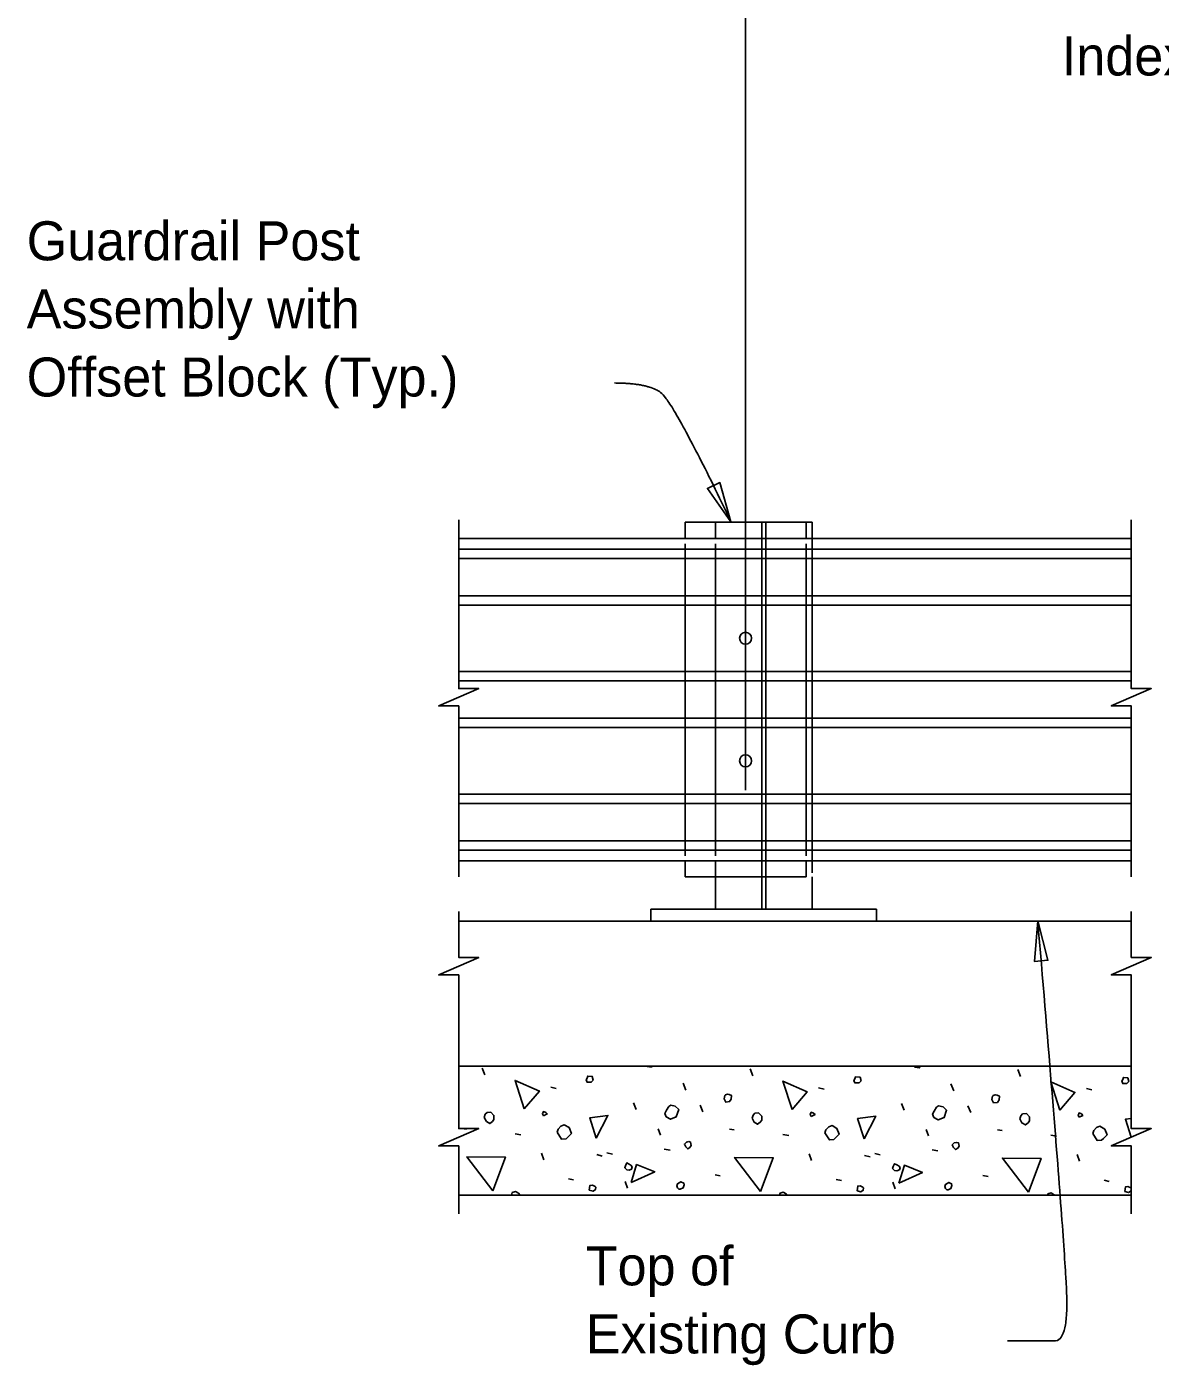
# Model space of a CAD drawing. Extents: x 21516.9 to 21589, y 56154.7 to 56194.3.
# Drawn here: x 21518.18 to 21524.04, y 56169.83 to 56176.75 of the extents above; entities that cross this region are included whole.
import ezdxf

# ---------------------------------------------------------------- set-up
doc = ezdxf.new("R2010")
doc.units = 0
for name, color, linetype in [('AdhocPoint_dp', 7, 'Continuous'), ('Border', 7, 'Continuous'), ('Patterning', 7, 'Continuous'), ('PlotBorder_dp', 7, 'Continuous'), ('TextMisc', 7, 'Continuous')]:
    doc.layers.add(name, color=color, linetype=linetype)

msp = doc.modelspace()

# ---------------------------------------------------------------- linework, layer by layer
at = {"layer": 'AdhocPoint_dp'}
for p, q in [((21523.8864, 56172.1237), (21520.4095, 56172.1237)), ((21520.4095, 56171.3737), (21523.8864, 56171.3737)), ((21523.8864, 56170.707), (21520.4095, 56170.707))]:
    msp.add_line(p, q, dxfattribs=at)
at = {"layer": 'Border'}
for p, q in [((21521.9758, 56172.1863), (21521.9758, 56174.1863)), ((21521.9967, 56172.1863), (21521.9967, 56174.1863)), ((21522.2363, 56174.1863), (21522.2363, 56172.3733)), ((21521.7363, 56174.0744), (21521.7363, 56172.4625))]:
    msp.add_line(p, q, dxfattribs=at)
at = {"layer": 'Patterning'}
for p, q in [((21521.58, 56174.1863), (21522.205, 56174.1863)), ((21521.58, 56174.1863), (21521.58, 56174.1029)), ((21522.205, 56174.1863), (21522.205, 56174.1029)), ((21521.58, 56174.0744), (21521.58, 56172.4625)), ((21522.205, 56174.0744), (21522.205, 56172.4625)), ((21521.58, 56172.3529), (21521.58, 56172.4363)), ((21522.205, 56172.3529), (21522.205, 56172.4363)), ((21521.58, 56172.3529), (21522.205, 56172.3529)), ((21520.545, 56171.3288), (21520.5309, 56171.3641)), ((21521.9297, 56171.3252), (21521.9156, 56171.3606)), ((21523.3144, 56171.3217), (21523.3002, 56171.3571)), ((21521.5838, 56171.2504), (21521.5697, 56171.2857)), ((21522.9685, 56171.2468), (21522.9544, 56171.2822)), ((21520.8856, 56171.2663), (21520.9139, 56171.2592)), ((21522.2703, 56171.2627), (21522.2985, 56171.2557)), ((21523.6549, 56171.2592), (21523.6832, 56171.2521)), ((21521.3275, 56171.1496), (21521.3134, 56171.185)), ((21521.6716, 56171.1379), (21521.6575, 56171.1732)), ((21522.7122, 56171.1461), (21522.6981, 56171.1814)), ((21523.0563, 56171.1343), (21523.0421, 56171.1697)), ((21520.4248, 56171.053), (21520.4496, 56171.0495)), ((21520.7006, 56171.0247), (21520.7306, 56171.0194)), ((21521.453, 56171.017), (21521.4407, 56171.0506)), ((21521.8095, 56171.0495), (21521.8342, 56171.0459)), ((21522.0853, 56171.0212), (21522.1153, 56171.0159)), ((21522.8377, 56171.0135), (21522.8253, 56171.0471)), ((21523.1942, 56171.0459), (21523.2189, 56171.0424)), ((21523.4699, 56171.0177), (21523.5, 56171.0123)), ((21520.8491, 56170.8904), (21520.8367, 56170.924)), ((21521.1755, 56170.9269), (21521.2038, 56170.9198)), ((21521.4719, 56170.9452), (21521.5019, 56170.9399)), ((21522.5602, 56170.9233), (21522.5885, 56170.9163)), ((21522.8565, 56170.9416), (21522.8866, 56170.9363)), ((21521.1231, 56170.9169), (21521.1514, 56170.9098)), ((21522.2338, 56170.8868), (21522.2214, 56170.9204)), ((21522.5078, 56170.9134), (21522.536, 56170.9063)), ((21523.6184, 56170.8833), (21523.6061, 56170.9169)), ((21520.9764, 56170.7914), (21521.0029, 56170.7861)), ((21521.7353, 56170.8126), (21521.7618, 56170.8073)), ((21522.361, 56170.7878), (21522.3876, 56170.7825)), ((21523.1199, 56170.8091), (21523.1464, 56170.8038)), ((21523.7457, 56170.7843), (21523.7722, 56170.779)), ((21521.2816, 56170.7443), (21521.2692, 56170.7779)), ((21522.6662, 56170.7407), (21522.6539, 56170.7743))]:
    msp.add_line(p, q, dxfattribs=at)
for points in [[(21521.3833, 56171.3737), (21521.3841, 56171.3723), (21521.4053, 56171.3688), (21521.408, 56171.3737)], [(21522.7661, 56171.3737), (21522.7688, 56171.3688), (21522.79, 56171.3653), (21522.7947, 56171.3737)], [(21520.7483, 56171.1538), (21520.7006, 56171.3005), (21520.8261, 56171.2457), (21520.7483, 56171.1538)], [(21521.073, 56171.291), (21521.0942, 56171.291), (21521.1048, 56171.3016), (21521.0995, 56171.3211), (21521.0765, 56171.3228), (21521.073, 56171.3122), (21521.0677, 56171.3034), (21521.073, 56171.291), (21521.0694, 56171.2946)], [(21522.133, 56171.1502), (21522.0853, 56171.297), (21522.2108, 56171.2422), (21522.133, 56171.1502)], [(21522.4576, 56171.2875), (21522.4789, 56171.2875), (21522.4895, 56171.2981), (21522.4842, 56171.3175), (21522.4612, 56171.3193), (21522.4576, 56171.3087), (21522.4523, 56171.2999), (21522.4576, 56171.2875), (21522.4541, 56171.291)], [(21523.5177, 56171.1467), (21523.4699, 56171.2934), (21523.5955, 56171.2386), (21523.5177, 56171.1467)], [(21523.8423, 56171.284), (21523.8635, 56171.284), (21523.8741, 56171.2946), (21523.8688, 56171.314), (21523.8459, 56171.3158), (21523.8423, 56171.3052), (21523.837, 56171.2963), (21523.8423, 56171.284), (21523.8388, 56171.2875)], [(21521.7812, 56171.205), (21521.7901, 56171.1891), (21521.8095, 56171.1909), (21521.8183, 56171.2033), (21521.8201, 56171.2227), (21521.8077, 56171.228), (21521.7989, 56171.2298), (21521.7883, 56171.2262), (21521.7847, 56171.2227), (21521.7812, 56171.205)], [(21523.1659, 56171.2015), (21523.1747, 56171.1856), (21523.1942, 56171.1874), (21523.203, 56171.1997), (21523.2048, 56171.2192), (21523.1924, 56171.2245), (21523.1836, 56171.2262), (21523.173, 56171.2227), (21523.1694, 56171.2192), (21523.1659, 56171.2015)], [(21520.5415, 56171.1096), (21520.5521, 56171.0884), (21520.5698, 56171.0778), (21520.5839, 56171.0884), (21520.591, 56171.099), (21520.591, 56171.1202), (21520.5751, 56171.1361), (21520.5556, 56171.1343), (21520.5468, 56171.1255), (21520.5415, 56171.1096)], [(21520.8473, 56171.1184), (21520.8668, 56171.1273), (21520.8597, 56171.1343), (21520.8473, 56171.1396), (21520.842, 56171.1273), (21520.8473, 56171.1184)], [(21521.4813, 56171.1125), (21521.5043, 56171.1001), (21521.5344, 56171.1125), (21521.5467, 56171.1496), (21521.529, 56171.1673), (21521.5061, 56171.1726), (21521.4955, 56171.1655), (21521.4831, 56171.1461), (21521.4742, 56171.1302), (21521.4813, 56171.1125)], [(21521.9262, 56171.106), (21521.9368, 56171.0848), (21521.9545, 56171.0742), (21521.9686, 56171.0848), (21521.9757, 56171.0954), (21521.9757, 56171.1166), (21521.9598, 56171.1326), (21521.9403, 56171.1308), (21521.9315, 56171.1219), (21521.9262, 56171.106)], [(21522.232, 56171.1149), (21522.2514, 56171.1237), (21522.2444, 56171.1308), (21522.232, 56171.1361), (21522.2267, 56171.1237), (21522.232, 56171.1149)], [(21522.866, 56171.1089), (21522.889, 56171.0966), (21522.919, 56171.1089), (21522.9314, 56171.1461), (21522.9137, 56171.1638), (21522.8907, 56171.1691), (21522.8801, 56171.162), (21522.8678, 56171.1425), (21522.8589, 56171.1266), (21522.866, 56171.1089)], [(21523.6167, 56171.1113), (21523.6361, 56171.1202), (21523.629, 56171.1273), (21523.6167, 56171.1326), (21523.6114, 56171.1202), (21523.6167, 56171.1113)], [(21520.918, 56171.0336), (21520.941, 56170.9964), (21520.964, 56170.9982), (21520.9728, 56171.007), (21520.9923, 56171.0265), (21520.9799, 56171.0565), (21520.9552, 56171.0707), (21520.9375, 56171.0636), (21520.9233, 56171.0495), (21520.918, 56171.0336)], [(21521.1207, 56171.0029), (21521.0871, 56171.1072), (21521.1808, 56171.1196), (21521.1207, 56171.0029)], [(21522.3027, 56171.03), (21522.3257, 56170.9929), (21522.3487, 56170.9947), (21522.3575, 56171.0035), (21522.377, 56171.023), (21522.3646, 56171.053), (21522.3398, 56171.0671), (21522.3221, 56171.0601), (21522.308, 56171.0459), (21522.3027, 56171.03)], [(21522.5054, 56170.9993), (21522.4718, 56171.1036), (21522.5655, 56171.116), (21522.5054, 56170.9993)], [(21523.3108, 56171.1025), (21523.3215, 56171.0813), (21523.3391, 56171.0707), (21523.3533, 56171.0813), (21523.3603, 56171.0919), (21523.3603, 56171.1131), (21523.3444, 56171.129), (21523.325, 56171.1273), (21523.3162, 56171.1184), (21523.3108, 56171.1025)], [(21523.6874, 56171.0265), (21523.7104, 56170.9894), (21523.7333, 56170.9911), (21523.7422, 56171), (21523.7616, 56171.0194), (21523.7493, 56171.0495), (21523.7245, 56171.0636), (21523.7068, 56171.0565), (21523.6927, 56171.0424), (21523.6874, 56171.0265)], [(21523.8864, 56171.0073), (21523.8565, 56171.1001), (21523.8864, 56171.1041)], [(21521.5832, 56170.9575), (21521.5938, 56170.9469), (21521.6044, 56170.954), (21521.6115, 56170.9646), (21521.608, 56170.9823), (21521.5991, 56170.9841), (21521.5868, 56170.9823), (21521.5762, 56170.9717), (21521.5832, 56170.9575)], [(21522.9679, 56170.954), (21522.9785, 56170.9434), (21522.9891, 56170.9505), (21522.9962, 56170.9611), (21522.9926, 56170.9788), (21522.9838, 56170.9805), (21522.9714, 56170.9788), (21522.9608, 56170.9682), (21522.9679, 56170.954)], [(21520.5857, 56170.7295), (21520.4513, 56170.9063), (21520.6511, 56170.9045), (21520.5857, 56170.7295)], [(21521.278, 56170.8385), (21521.2904, 56170.8367), (21521.3028, 56170.842), (21521.3063, 56170.8526), (21521.301, 56170.8615), (21521.2904, 56170.8685), (21521.278, 56170.8738), (21521.271, 56170.8597), (21521.2674, 56170.8491), (21521.278, 56170.8385)], [(21521.3004, 56170.7737), (21521.3287, 56170.8656), (21521.4224, 56170.8285), (21521.3004, 56170.7737)], [(21521.9704, 56170.726), (21521.836, 56170.9027), (21522.0358, 56170.901), (21521.9704, 56170.726)], [(21522.6627, 56170.8349), (21522.6751, 56170.8332), (21522.6875, 56170.8385), (21522.691, 56170.8491), (21522.6857, 56170.8579), (21522.6751, 56170.865), (21522.6627, 56170.8703), (21522.6556, 56170.8562), (21522.6521, 56170.8456), (21522.6627, 56170.8349)], [(21522.6851, 56170.7702), (21522.7133, 56170.8621), (21522.807, 56170.825), (21522.6851, 56170.7702)], [(21523.355, 56170.7224), (21523.2207, 56170.8992), (21523.4204, 56170.8974), (21523.355, 56170.7224)], [(21520.7268, 56170.707), (21520.7271, 56170.7083), (21520.7183, 56170.7171), (21520.7024, 56170.726), (21520.6864, 56170.7207), (21520.6819, 56170.707)], [(21521.0842, 56170.733), (21521.1036, 56170.7277), (21521.116, 56170.7366), (21521.1178, 56170.749), (21521.1142, 56170.7525), (21521.1001, 56170.7596), (21521.0877, 56170.7578), (21521.086, 56170.7454), (21521.0842, 56170.733)], [(21521.5479, 56170.7383), (21521.5549, 56170.7383), (21521.5691, 56170.7454), (21521.5744, 56170.7613), (21521.5726, 56170.7702), (21521.5585, 56170.7772), (21521.5408, 56170.7666), (21521.5373, 56170.756), (21521.5408, 56170.7454), (21521.5479, 56170.7383)], [(21522.1095, 56170.707), (21522.1029, 56170.7136), (21522.087, 56170.7224), (21522.0711, 56170.7171), (21522.0678, 56170.707)], [(21522.4689, 56170.7295), (21522.4883, 56170.7242), (21522.5007, 56170.733), (21522.5025, 56170.7454), (21522.4989, 56170.749), (21522.4848, 56170.756), (21522.4724, 56170.7543), (21522.4706, 56170.7419), (21522.4689, 56170.7295)], [(21522.9325, 56170.7348), (21522.9396, 56170.7348), (21522.9538, 56170.7419), (21522.9591, 56170.7578), (21522.9573, 56170.7666), (21522.9432, 56170.7737), (21522.9255, 56170.7631), (21522.9219, 56170.7525), (21522.9255, 56170.7419), (21522.9325, 56170.7348)], [(21523.4907, 56170.707), (21523.4876, 56170.7101), (21523.4717, 56170.7189), (21523.4558, 56170.7136), (21523.4536, 56170.707)], [(21523.8864, 56170.7427), (21523.8836, 56170.7454), (21523.8695, 56170.7525), (21523.8571, 56170.7507), (21523.8553, 56170.7383), (21523.8536, 56170.726)], [(21523.8536, 56170.726), (21523.873, 56170.7207), (21523.8854, 56170.7295), (21523.8864, 56170.7364)]]:
    msp.add_lwpolyline(points, dxfattribs=at)
at = {"layer": 'PlotBorder_dp'}
msp.add_line((21521.8925, 56172.8011), (21521.8925, 56187.0498), dxfattribs=at)
for points in [[(21521.8169, 56174.1882), (21521.7591, 56174.3914), (21521.6954, 56174.361)], [(21523.4031, 56172.1265), (21523.3855, 56171.916), (21523.4558, 56171.922)]]:
    msp.add_lwpolyline(points, close=True, dxfattribs=at)
for points in [[(21520.4095, 56172.3532), (21520.4095, 56173.2364), (21520.3062, 56173.2364), (21520.4095, 56173.2814), (21520.5129, 56173.3264), (21520.4095, 56173.3264), (21520.4095, 56174.1994)], [(21523.8864, 56172.3532), (21523.8864, 56173.2364), (21523.783, 56173.2364), (21523.8864, 56173.2814), (21523.9897, 56173.3264), (21523.8864, 56173.3264), (21523.8864, 56174.1994)], [(21520.4095, 56171.3763), (21520.4095, 56171.8464), (21520.3062, 56171.8464), (21520.4095, 56171.8914), (21520.5129, 56171.9364), (21520.4095, 56171.9364), (21520.4095, 56172.1738)], [(21523.8864, 56171.3763), (21523.8864, 56171.8464), (21523.783, 56171.8464), (21523.8864, 56171.8914), (21523.9897, 56171.9364), (21523.8864, 56171.9364), (21523.8864, 56172.1738)], [(21520.4095, 56170.6112), (21520.4095, 56170.9619), (21520.3062, 56170.9619), (21520.4095, 56171.0069), (21520.5129, 56171.0519), (21520.4095, 56171.0519), (21520.4095, 56171.3763)], [(21523.8864, 56170.6112), (21523.8864, 56170.9619), (21523.783, 56170.9619), (21523.8864, 56171.0069), (21523.9897, 56171.0519), (21523.8864, 56171.0519), (21523.8864, 56171.3763)]]:
    msp.add_lwpolyline(points, dxfattribs=at)
for points in [[(21521.2155, 56174.9059), (21521.3857, 56174.9059), (21521.5219, 56174.8066), (21521.8169, 56174.1882)], [(21523.2461, 56169.9544), (21523.4292, 56169.9544), (21523.5535, 56169.9544), (21523.5535, 56170.3469), (21523.4031, 56172.1265)]]:
    msp.add_open_spline(points, degree=2, dxfattribs=at)
at = {"layer": 'TextMisc'}
for p, q in [((21521.7363, 56174.1863), (21522.2363, 56174.1863)), ((21521.7363, 56174.1863), (21521.7363, 56174.1029)), ((21520.4095, 56174.1029), (21523.8864, 56174.1029)), ((21523.8864, 56174.0473), (21520.4095, 56174.0473)), ((21523.8864, 56173.9991), (21520.4095, 56173.9991)), ((21523.8864, 56173.8063), (21520.4095, 56173.8063)), ((21523.8864, 56173.7581), (21520.4095, 56173.7581)), ((21523.8864, 56173.4141), (21520.4095, 56173.4141)), ((21523.8864, 56173.3659), (21520.4095, 56173.3659)), ((21523.8864, 56173.1731), (21520.4095, 56173.1731)), ((21523.8864, 56173.1249), (21520.4095, 56173.1249)), ((21523.8864, 56172.781), (21520.4095, 56172.781)), ((21523.8864, 56172.7328), (21520.4095, 56172.7328)), ((21523.8864, 56172.5399), (21520.4095, 56172.5399)), ((21523.8864, 56172.4917), (21520.4095, 56172.4917)), ((21520.4095, 56172.4362), (21523.8864, 56172.4362)), ((21521.7363, 56172.4363), (21521.7363, 56172.1863)), ((21522.2363, 56172.3529), (21522.2363, 56172.1863)), ((21521.4029, 56172.1863), (21522.5696, 56172.1863)), ((21521.4029, 56172.1238), (21521.4029, 56172.1863)), ((21521.7363, 56172.1863), (21522.2363, 56172.1863)), ((21522.5696, 56172.1863), (21522.5696, 56172.1238)), ((21521.4029, 56172.1238), (21522.5696, 56172.1238))]:
    msp.add_line(p, q, dxfattribs=at)
for centre in [(21521.8925, 56173.5862), (21521.8925, 56172.953)]:
    msp.add_circle(centre, 0.0312, dxfattribs=at)

# ---------------------------------------------------------------- texts
at = {"layer": 'PlotBorder_dp'}
for s, p in [('Index 460-470, Sheet 2) (Typ.)', (21523.5274, 56176.4955)), ('Guardrail Post ', (21518.1754, 56175.5401)), ('Assembly with ', (21518.1754, 56175.1881)), ('Offset Block (Typ.)', (21518.1754, 56174.8361)), ('Top of ', (21521.0659, 56170.2412)), ('Existing Curb', (21521.0659, 56169.8892))]:
    msp.add_text(s, height=0.2016, dxfattribs=at).set_placement(p)

doc.saveas('drawing.dxf')
